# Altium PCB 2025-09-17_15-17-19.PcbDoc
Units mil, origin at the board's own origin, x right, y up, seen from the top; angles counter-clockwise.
Board outline 3850 x 3650 mil, 4 copper layers (Top Layer, MidLayer1, MidLayer2, Bottom Layer); 64 components, 29 nets, 175 pads, 336 vias.
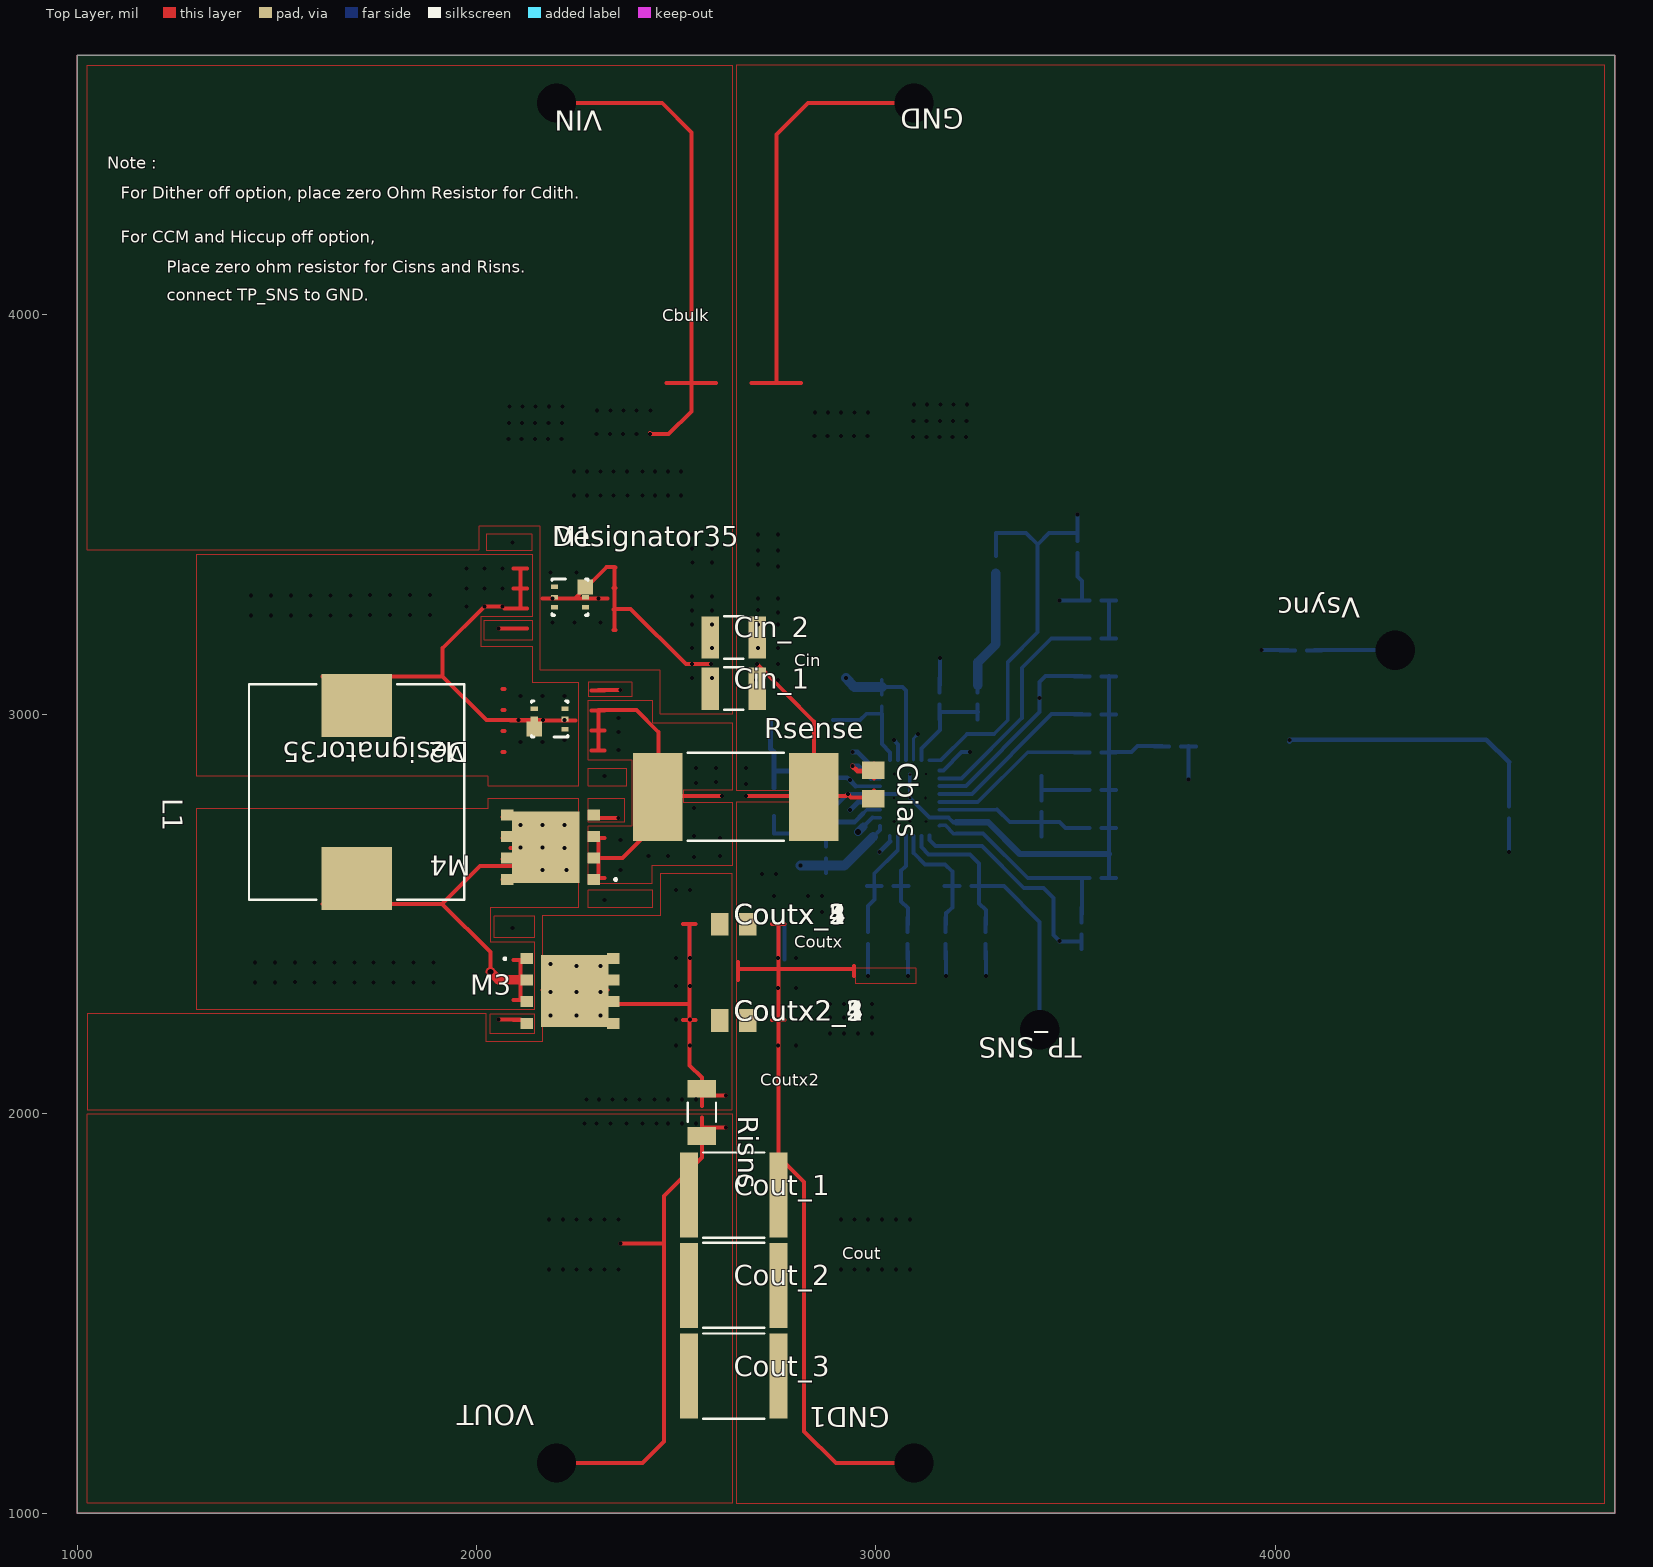
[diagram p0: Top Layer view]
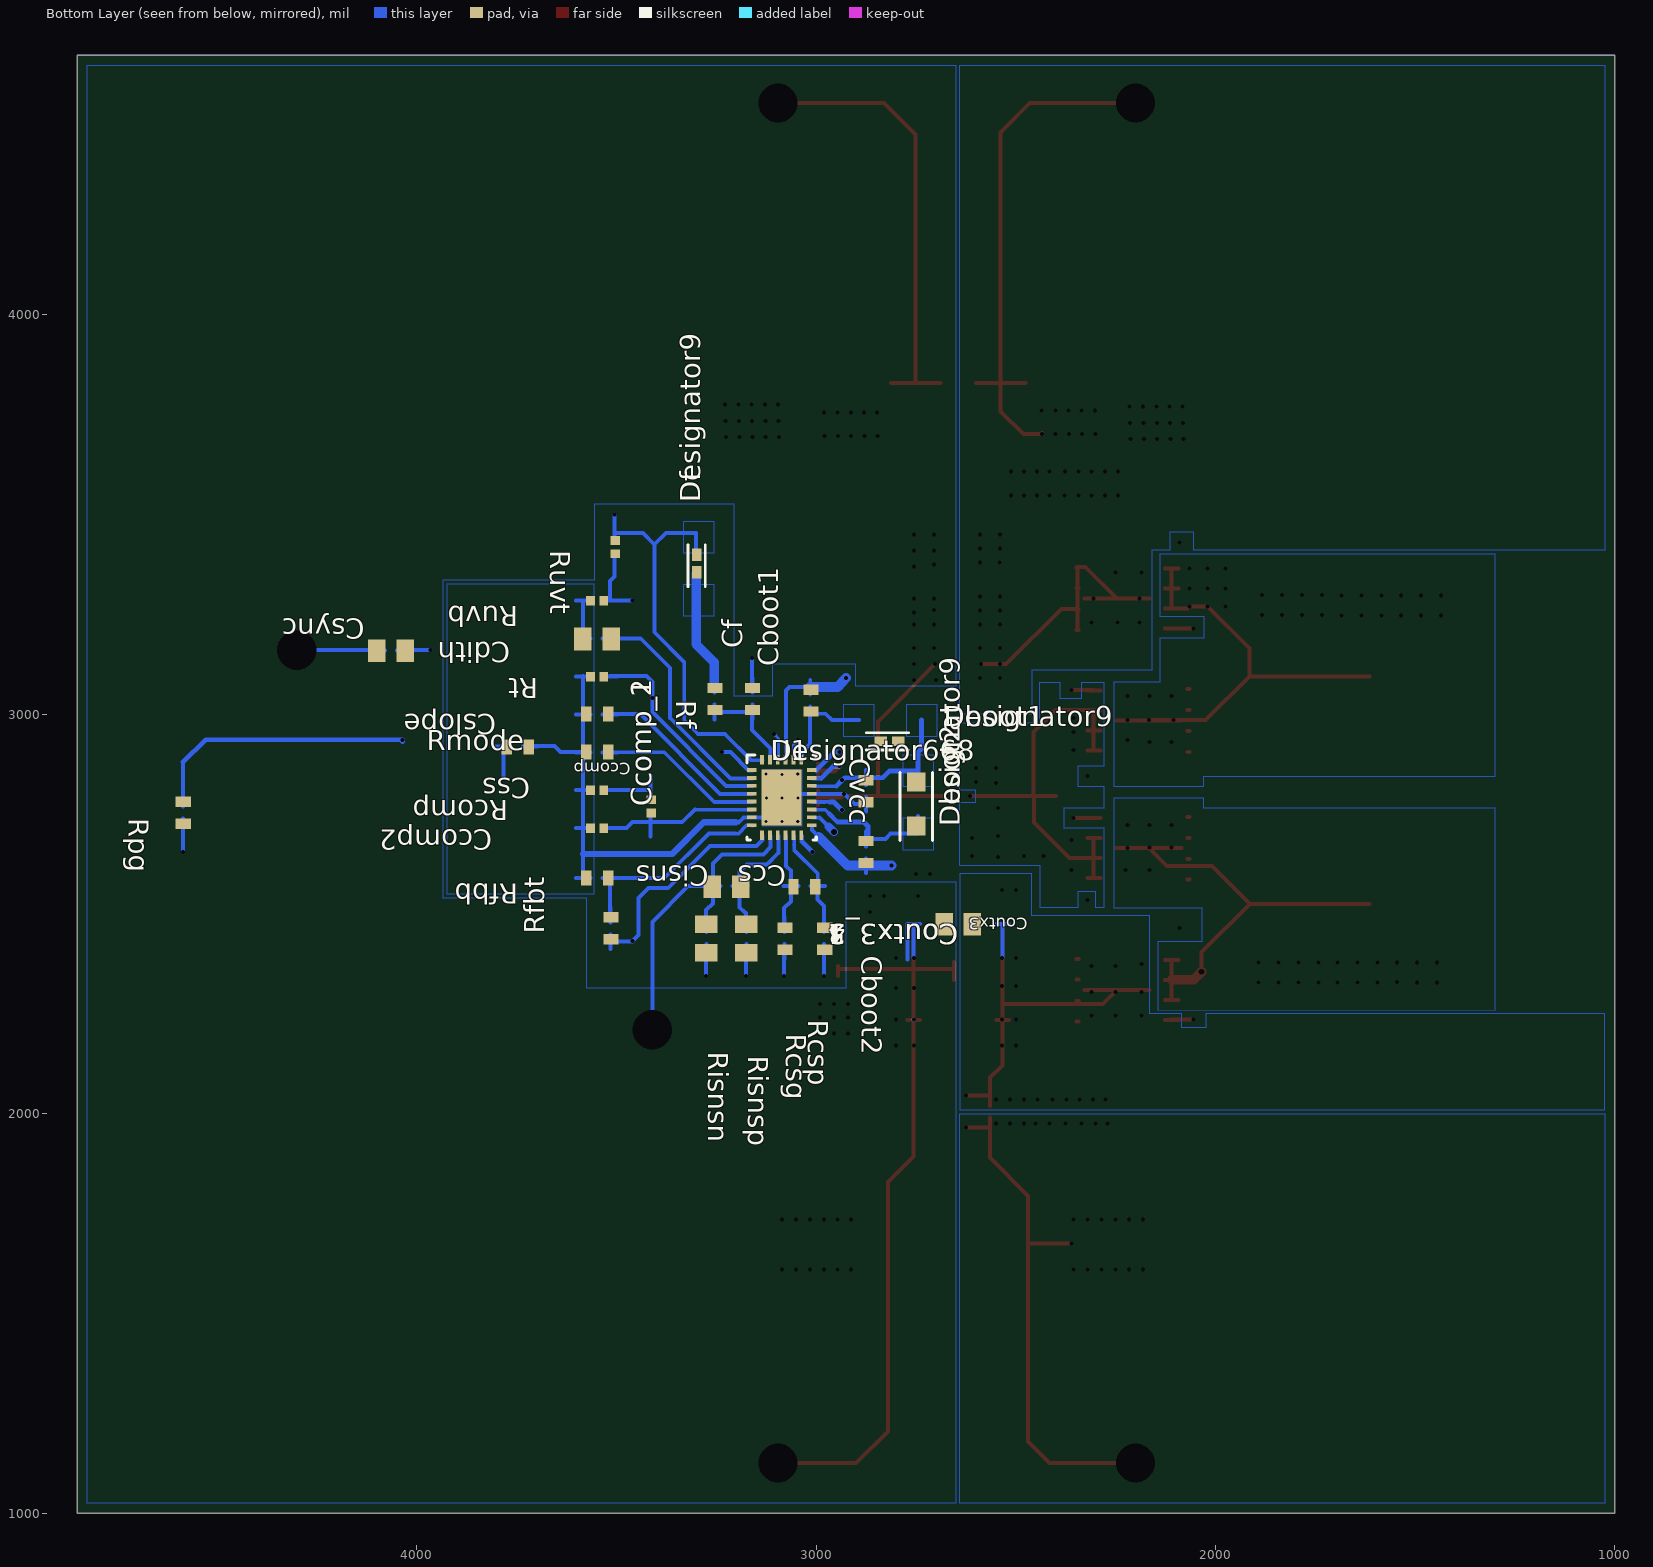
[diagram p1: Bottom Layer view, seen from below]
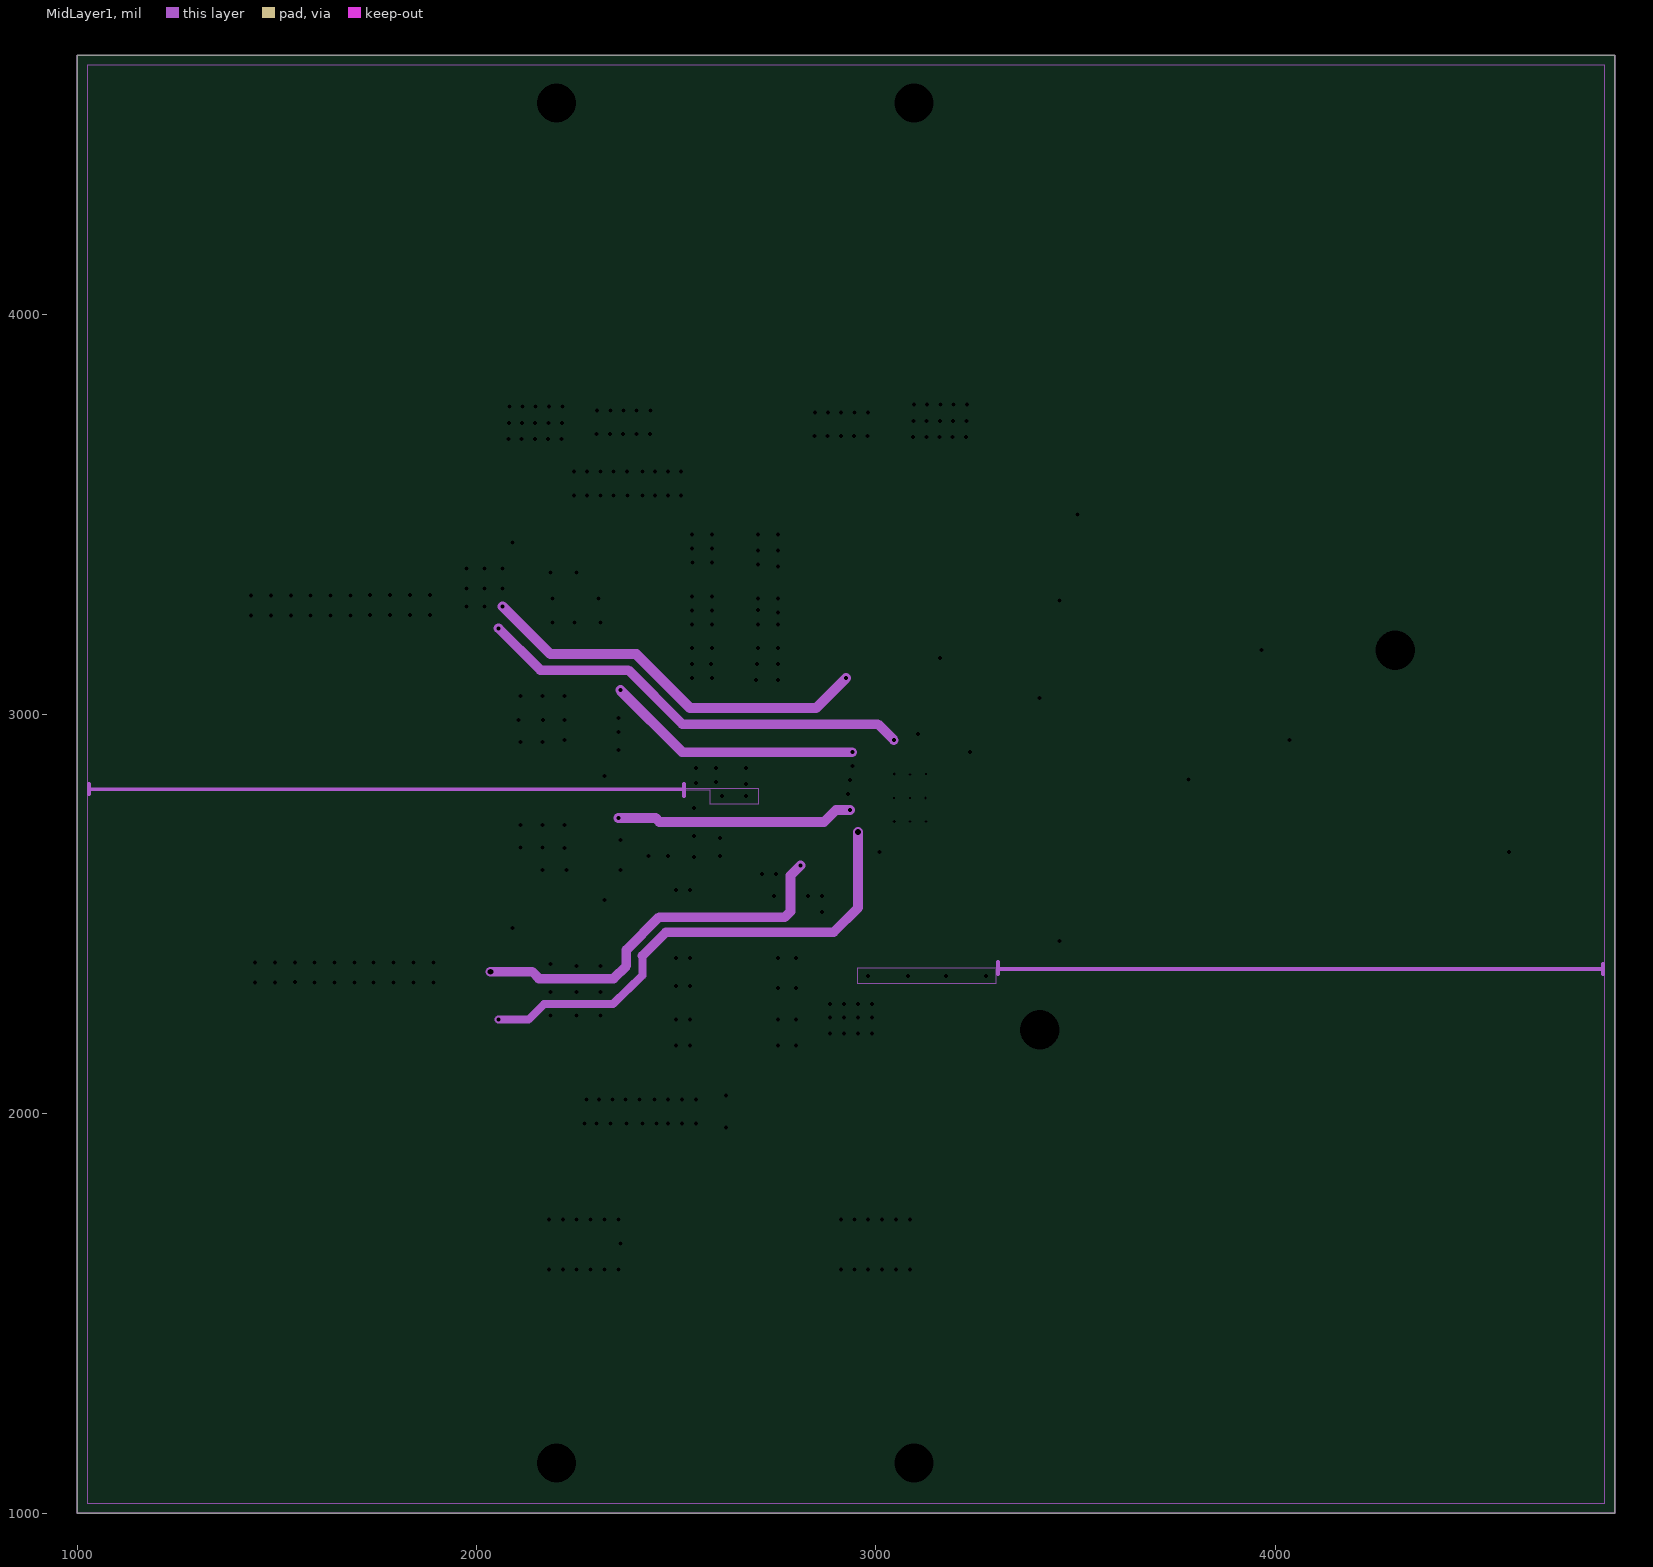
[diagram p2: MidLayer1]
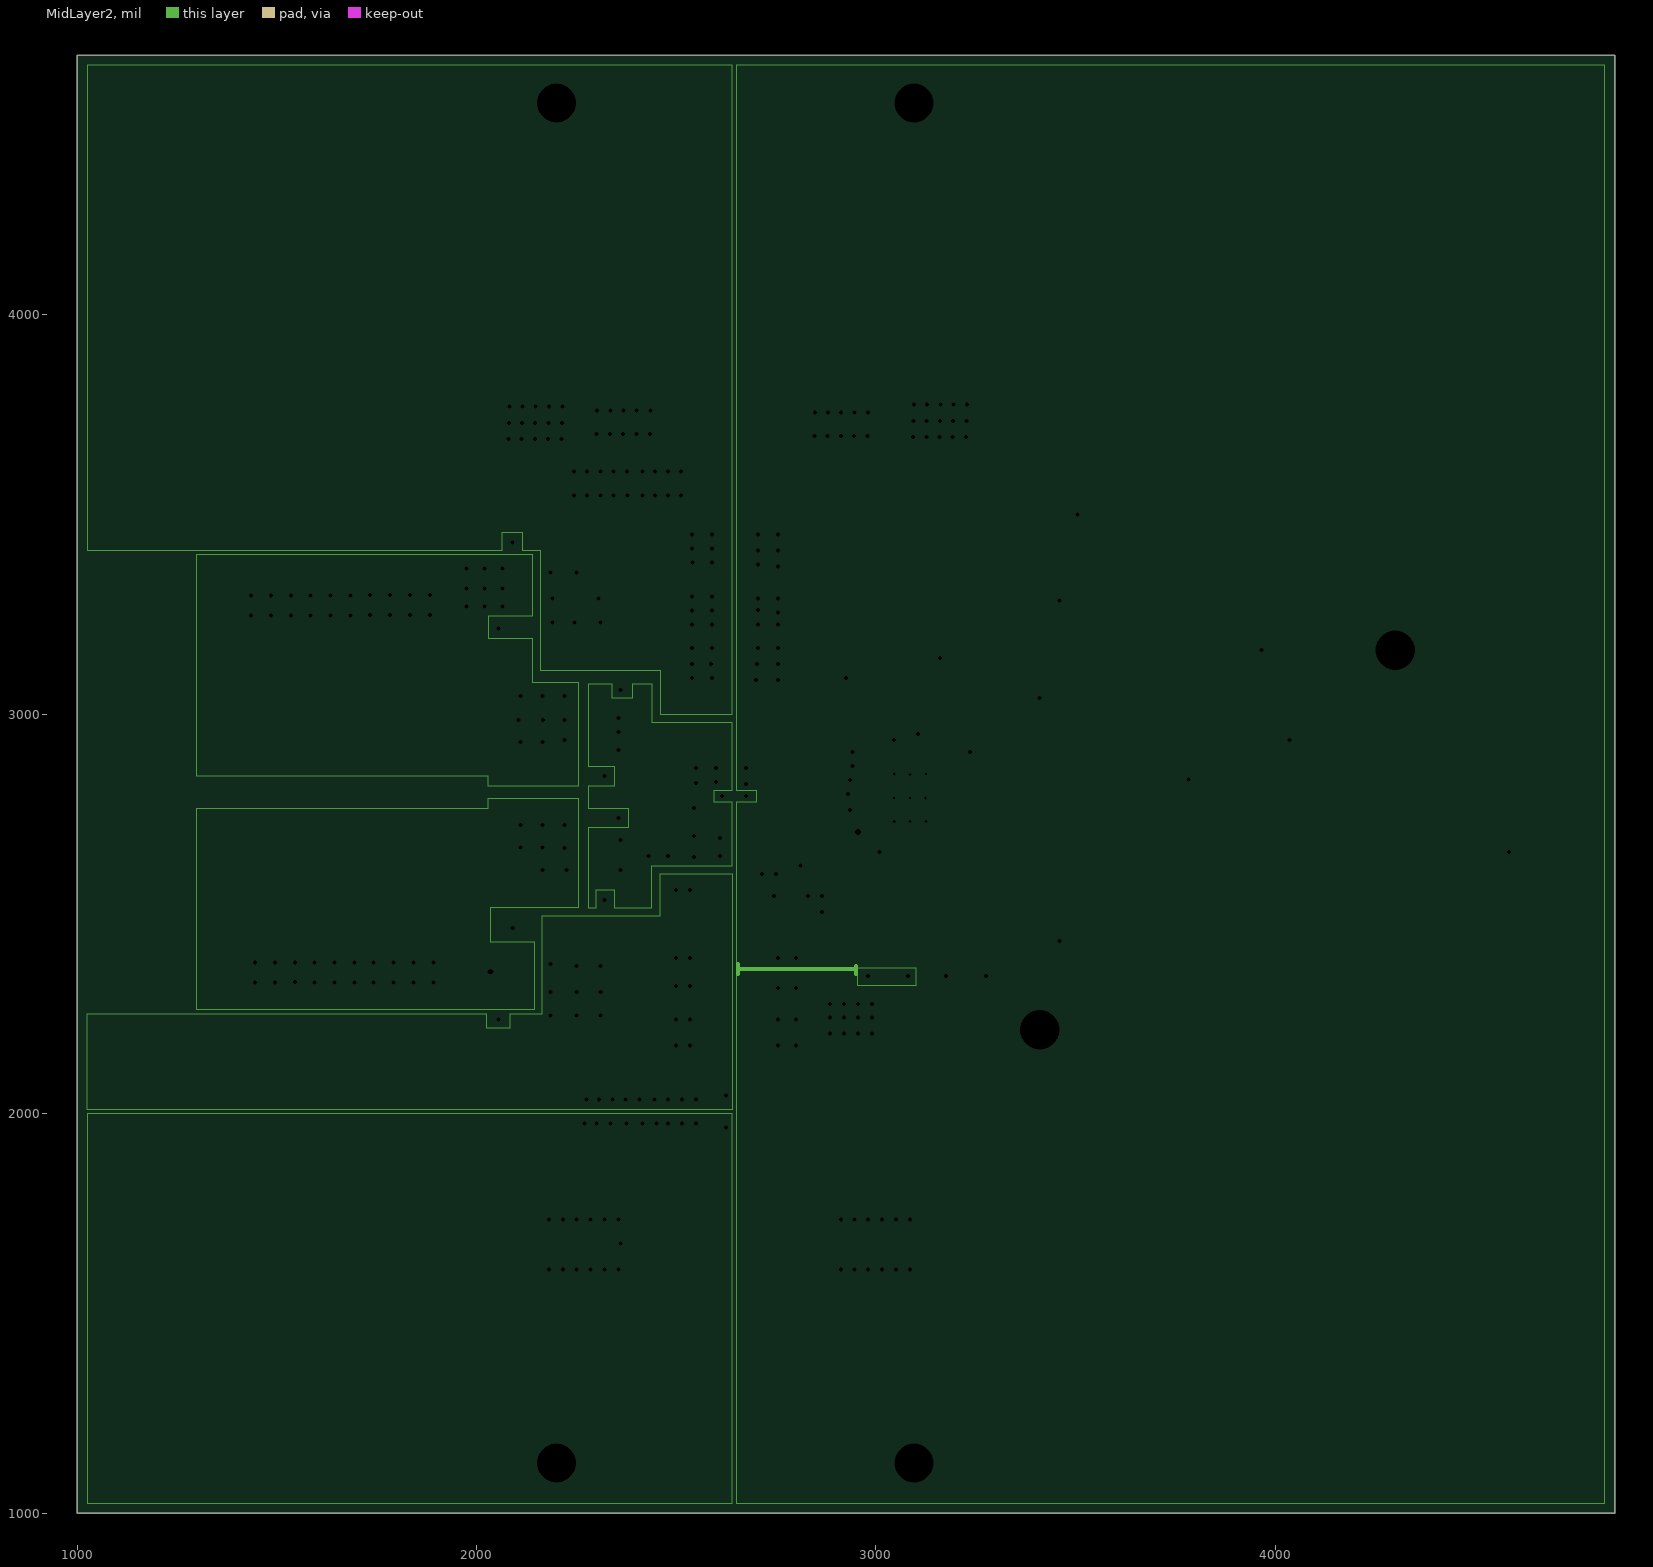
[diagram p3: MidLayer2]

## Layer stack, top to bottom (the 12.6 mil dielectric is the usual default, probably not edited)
Top Layer: signal copper 1.4
Dielectric: core 12.6, FR-4, Dk 4.8
MidLayer1: signal copper 1.4
Dielectric: prepreg 12.6, FR-4, Dk 4.8
MidLayer2: signal copper 1.4
Dielectric: core 12.6, FR-4, Dk 4.8
Bottom Layer: signal copper 1.4

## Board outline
1000,1000 4850,1000 4850,4650 1000,4650

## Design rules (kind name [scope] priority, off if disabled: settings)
PlaneConnect [All] p0: scope1count=1 scope1_0_kind=Board scope1_0_value=Board scope2count=1 scope2_0_kind=Board scope2_0_value=Board commentlength=0 planeconnectstyle=Direct reliefexpansion=20 reliefentries=4 reliefconductorwidth=10 reliefairgap=10
PlaneConnect [All] p1: planeconnectstyle=Direct reliefexpansion=20 reliefentries=4 reliefconductorwidth=10 reliefairgap=10
PolygonConnect [All] p0: scope1count=1 scope1_0_kind=Board scope1_0_value=Board scope2count=1 scope2_0_kind=Board scope2_0_value=Board commentlength=0 connectstyle=Direct reliefconductorwidth=10 reliefentries=4 polygonreliefangle="90 Angle"
PolygonConnect [All] p1: connectstyle=Direct reliefconductorwidth=10 reliefentries=4 polygonreliefangle="90 Angle"

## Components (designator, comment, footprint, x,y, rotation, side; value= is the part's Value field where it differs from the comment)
Cbias "" 0805#1 2993,2824 r270 top
Cboot1 "" 0603 3013,3034 r270 bottom
Cboot2 "" 0603 2875,2655 r90 bottom
Ccomp2 "" 0402 3548,2714 r180 bottom
Ccomp_1 "" 0402 3413,2769 r270 bottom
Ccomp_2 "" 0402 3413,2769 r270 bottom
Ccs "" 0603 3029,2568 r180 bottom
Cdith "" 0805#2 3548,3188 r180 bottom
Cf "" 0603 3159,3038 r270 bottom
Cin_1 "" 1210 2644,3064 r0 top
Cin_2 "" 1210 2644,3192 r0 top
Cisns "" 0805#2 3224,2568 r180 bottom
Cout_1 "" 2220_280 2644,1796 r0 top
Cout_2 "" 2220_280 2644,1570 r0 top
Cout_3 "" 2220_280 2644,1343 r0 top
Coutx2_1 "" 0805#1 2644,2233 r0 top
Coutx2_2 "" 0805#1 2644,2233 r0 top
Coutx2_3 "" 0805#1 2644,2233 r0 top
Coutx2_4 "" 0805#1 2644,2233 r0 top
Coutx2_5 "" 0805#1 2644,2233 r0 top
Coutx3_1 "" 0805#2 2644,2474 r180 bottom
Coutx3_2 "" 0805#2 2644,2474 r180 bottom
Coutx3_3 "" 0805#2 2644,2474 r180 bottom
Coutx3_4 "" 0805#2 2644,2474 r180 bottom
Coutx3_5 "" 0805#2 2644,2474 r180 bottom
Coutx_1 "" 0805#1 2644,2474 r0 top
Coutx_2 "" 0805#1 2644,2474 r0 top
Coutx_3 "" 0805#1 2644,2474 r0 top
Coutx_4 "" 0805#1 2644,2474 r0 top
Coutx_5 "" 0805#1 2644,2474 r0 top
Cslope "" 0603 3548,3000 r180 bottom
Css "" 0603 3548,2905 r180 bottom
Csync "" 0805#2 4064,3159 r180 bottom
Cvcc "" 0603 2875,2807 r90 bottom
Dboot1 "" SOD-523 2816,2932 r0 bottom
Dboot2 "" SOD-123F 2749,2775 r270 bottom
Df "" SOD-523 3299,3377 r270 bottom
GND "" TP-1502 3094,4529 r180 top
GND1 "" TP-1502 3094,1125 r180 top
L1 "" SRP1270 1700,2805 r270 top
M1 "" DQK0006C 2234,3293 r0 top
M2 "" DQK0006C 2183,2988 r180 top
M3 "" TRANS_NexFET_Q5A 2234,2307 r0 top
M4 "" TRANS_NexFET_Q5A 2185,2667 r180 top
Rcomp "" 0402 3548,2809 r180 bottom
Rcsg "" 0603 3078,2438 r90 bottom
Rcsp "" 0603 2978,2438 r90 bottom
Rf "" 0603 3253,3038 r90 bottom
Rfbb "" 0603 3548,2590 r180 bottom
Rfbt "" 0603 3513,2464 r270 bottom
Risns "" 1206 2564,2003 r270 top
Risnsn "" 0805#2 3275,2438 r90 bottom
Risnsp "" 0805#2 3175,2438 r90 bottom
Rmode "" 0603 3747,2918 r0 bottom
Rpg "" 0603 4584,2753 r90 bottom
Rsense "" 4527 2649,2793 r0 top
Rt "" 0402 3548,3094 r180 bottom
Ruvb "" 0402 3548,3284 r180 bottom
Ruvt "" 0402 3503,3418 r90 bottom
TP_SNS "" TP-1502 3409,2209 r180 top
U1 "" RHF0028A 3086,2791 r0 bottom
VIN "" TP-1502 2198,4529 r180 top
VOUT "" TP-1502 2198,1125 r180 top
Vsync "" TP-1502 4298,3159 r180 top

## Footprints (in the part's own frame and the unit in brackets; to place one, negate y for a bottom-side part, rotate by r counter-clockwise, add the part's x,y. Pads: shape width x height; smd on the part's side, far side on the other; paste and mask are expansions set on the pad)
0402 [mil]
  rect 22x24 smd: 1(16.5,0) 2(-16.5,0)
0603 [mil]
  rect 26x38 smd: 1(27.5,0) 2(-27.5,0)
0805#1 [mil]
  rect 44x57 smd: 1(-35.5,0) 2(35.5,0)
0805#2 [mil]
  rect 44x57 smd: 1(35.5,0) 2(-35.5,0)
1206 [mil]
  rect 44x71 smd: 1(-59,0) 2(59,0)
  silkscreen extent -24,-36 24,36
1210 [mil]
  rect 44x106 smd: 1(-59,0) 2(59,0)
  silkscreen extent -24,-53 24,53
2220_280 [mil]
  rect 45x213 smd: 1(-111.5,0) 2(111.5,0)
  silkscreen extent -76,-106 76,106
4527 [mil]
  rect 124x220 smd: 1(-195.5,0) 2(195.5,0)
  silkscreen extent -120,-110 120,110
DQK0006C [mm]
  rect 0.45x0.3 smd: 1(-0.975,0.65) 2(-0.975,0) 3(-0.975,-0.65) 4(0.975,-0.65) 5(0.975,0) 6(0.975,0.65)
  rect 0.75x0.3 smd: 6(0.975,0.65)
  rect 1x0.95 smd: 6(0.975,0.65)
  silkscreen extent -1.15,-1.15 1.15,1.15
RHF0028A [mm]
  rect 0.6x0.24 smd: 1(1.9,-1.75) 2(1.9,-1.25) 3(1.9,-0.75) 4(1.9,-0.25) 5(1.9,0.25) 6(1.9,0.75) 7(1.9,1.25) 8(1.9,1.75) 15(-1.9,1.75) 16(-1.9,1.25) 17(-1.9,0.75) 18(-1.9,0.25) 19(-1.9,-0.25) 20(-1.9,-0.75) 21(-1.9,-1.25) 22(-1.9,-1.75)
  rect 0.24x0.6 smd: 9(1.25,2.4) 10(0.75,2.4) 11(0.25,2.4) 12(-0.25,2.4) 13(-0.75,2.4) 14(-1.25,2.4) 23(-1.25,-2.4) 24(-0.75,-2.4) 25(-0.25,-2.4) 26(0.25,-2.4) 27(0.75,-2.4) 28(1.25,-2.4)
  rect 2.55x3.55 smd: 29(0,0)
  silkscreen extent -2.2,-2.7 2.2,2.7
SOD-123F [mm]
  rect 1.2x1.2 smd: 1(1.4,0) 2(-1.4,0)
  silkscreen extent -2.01,-1.03 2.31,1.03
SOD-523 [mm]
  rect 0.8x0.6 smd: 1(0.55,0) 2(-0.55,0)
  silkscreen extent -1.2,-0.55 1.48,0.55
SRP1270 [mil]
  rect 157.5x177 smd: 1(-216.75,0) 2(216.75,0)
  silkscreen extent -270,-270 270,270
TP-1502 [mil]
  round 65 hole 32: 1(0,0)
TRANS_NexFET_Q5A [mm]
  rect 0.8x0.7 smd: 1(-2.752,2.055) 2(-2.752,0.685) 3(-2.752,-0.685) 4(-2.752,-2.055) 5(2.752,-2.055) 6(2.752,-0.685) 7(2.752,0.685) 8(2.752,2.055)
  rect 4.3x4.56 smd: 9(0.3,0)
  silkscreen extent -4.22,1.98 -4.07,2.13

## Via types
v1: diameter 0, hole 10, Top Layer to Bottom Layer, 319 vias
v2: diameter 0, hole 8, Top Layer to Bottom Layer, 9 vias
v3: diameter 0, hole 98, Top Layer to Bottom Layer, 6 vias
v4: diameter 0, hole 14, Top Layer to Bottom Layer, 2 vias

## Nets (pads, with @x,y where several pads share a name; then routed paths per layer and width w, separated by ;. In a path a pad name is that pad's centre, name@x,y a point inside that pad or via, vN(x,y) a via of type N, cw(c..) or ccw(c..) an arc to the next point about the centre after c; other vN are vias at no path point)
0: Cbias.2 Ccomp2.2 Cdith.2 Cf.2 Cin_1.2 Cin_2.2 Cout_1.2 Cout_2.2 Cout_3.2 Coutx2_1.2 Coutx2_2.2 Coutx2_3.2 Coutx2_4.2 Coutx2_5.2 Coutx3_1.2 Coutx3_2.2 Coutx3_3.2 Coutx3_4.2 Coutx3_5.2 Coutx_1.2 Coutx_2.2 Coutx_3.2 Coutx_4.2 Coutx_5.2 Cslope.2 Css.2 Cvcc.2 GND1.1 GND.1 Rcomp.2 Rcsg.2 Rfbb.2 Rmode.2 Rsense.2 Rt.2 Ruvb.2 U1.7 U1.19 U1.29 | length 12480.1
  Top Layer w10: 2655,2335 2655,2362 ; 2655,2380 2655,2362 ; v1(2675,2795) Rsense.2@2845,2795 ; 2689,3829 2812,3829 ; v1(2702,3125) 2845,2981 Rsense.2@2845,2795 ; 2740,2234.5 2771,2234.5 ; 2740,2474.5 2771,2474.5 ; 2751,3830 2751,4451 2830,4530 v3(3095,4530) ; 2756,2475 2756,2362 ; Rsense.2@2790,2795 Rsense.2@2900,2795 ; 2945,2345 2945,2362 ; 2945,2370 2945,2362 ; Cbias.2@2994.5,2772 Cbias.2@2994.5,2809 ; Cbias.2@2995,2791 2938,2791 v1(2930,2800) 2925,2795 Rsense.2@2845,2795 ; v3(3095,1125) 2900,1125 2820,1204 2820,1675 2820,1829 2756,1893 2756,2235 2756,2362 ; 2655,2362 2756,2362 ; 2756,2362 2945,2362
  MidLayer1 w10: 1030,2800 1030,2812 ; 1030,2825 1030,2812 ; 2519,2812 1030,2812 ; 2520,2795 2520,2825 ; 3305,2350 3305,2362 ; 3305,2380 3305,2362 ; 4820,2350 4820,2362 ; 4820,2375 4820,2362 ; 3305,2362 4820,2362
  MidLayer2 w10: 2655,2350 2655,2362 ; 2655,2375 2655,2362 ; 2950,2350 2950,2362 ; 2950,2370 2950,2362 ; 2655,2362 2950,2362
  Mid-Layer 3 w10: 1030,2801 1030,2830 ; 1030,2812 2510,2812 ; 2510,2795 2510,2812 ; 2510,2830 2510,2812 ; 2670,2795 v1(2675,2795) 2655,2775 2655,2490 2685,2460 3010,2460 3040,2430 3040,2385 v1(3080,2345)
  Mid-Layer 4 w10: 2655,2350 2655,2362 ; 2655,2375 2655,2362 ; 2919,2362 2655,2362 ; 2920,2350 2920,2375
  Bottom Layer w9: 2962,2800 3010,2800 3045,2800 U1.29@3061,2800 ; v2(3085,2790) v2(3085,2849)
  Bottom Layer w10: 2740,2474.5 2771,2474.5 ; v1(2755,2235) 2756,2236 ; 2756,2391 2756,2475 ; 2771,2386 2771,2475 ; 2874.5,2756 2874.5,2793 ; Cvcc.2@2875,2775 2904,2775 2929,2800 ; v1(2930,2800) 2929,2800 ; 2962,2800 2929,2800 ; 3079.5,2387 3079.5,2424 ; v1(3080,2345) Rcsg.2@3080,2406 ; v2(3085,2790) 3134,2741 3159,2741 3181,2741 3194,2729 3201,2729 ; Cf.2@3159.5,3054 3159.5,3091 ; Cf.2@3160,3073 v1(3160,3140) ; Rfbb.2@3564,2589.5 3601,2589.5 ; Ccomp2.2@3564,2714.5 3601,2714.5 ; Rcomp.2@3564,2809.5 3601,2809.5 ; Css.2@3564,2904.5 3601,2904.5 ; Cslope.2@3564,2999.5 3601,2999.5 ; Rt.2@3564,3094.5 3601,3094.5 ; Cdith.2@3564,3189.5 Cdith.2@3601,3189.5 ; Ruvb.2@3564,3284.5 3601,3284.5 ; Rfbb.2@3583,2590 3583,2650 3583,2715 3583,2810 Css.2@3583,2905 ; 3583,3095 3583,3000 Css.2@3583,2905 ; Cdith.2@3583,3190 3583,3285 ; 3697,2919.5 3734,2919.5 ; Rmode.2@3716,2920 3655,2920 3640,2905 Css.2@3583,2905
  Bottom Layer w16: 3201,2729 3281,2729 3360,2650 3583,2650
  other v1: 2912,1610 2946,1610 2980,1610 3015,1610 3050,1610 3085,1610 2912,1735 2946,1735 2980,1735 3015,1735 3050,1735 3085,1735 2755,2170 2800,2170 2885,2200 2920,2200 2955,2200 2990,2200 2800,2235 2885,2240 2920,2240 2955,2240 2990,2240 2885,2275 2920,2275 2955,2275 2990,2275 2755,2315 2800,2315 2755,2390 2800,2390 2865,2505 2745,2545 2830,2545 2865,2545 2715,2600 2750,2600 2675,2825 2675,2865 2700,3085 2755,3085 2755,3125 2705,3165 2755,3165 2705,3225 2755,3225 2755,3255 2705,3261 2705,3290 2755,3290 2755,3370 2705,3375 2705,3410 2755,3410 2705,3450 2755,3450 3093,3694 3126,3694 3159,3694 3192,3694 3226,3694 2846,3696 2879,3696 2912,3696 2945,3696 2979,3696 3094,3734 3127,3734 3160,3734 3193,3734 3227,3734 2847,3755 2880,3755 2913,3755 2946,3755 2980,3755 3095,3775 3128,3775 3161,3775 3194,3775 3228,3775
  other v2: 3046,2731 3085,2731 3125,2731 3045,2790 3124,2790 3046,2850 3125,2850
1: Cin_1.1 Cin_2.1 Df.2 M1.1 M1.2 M1.3 M1.5 M1.6 Ruvt.1 U1.28 VIN.1 | length 4321.1
  Top Layer w10: 2165,3289.5 2328,3289.5 ; v3(2200,4530) 2465,4530 2538,4456 2538,3830 2538,3758 2481,3701 v1(2434,3701) 2434,3704 ; 2247,3290 2326,3368 2346,3368 2346,3316 2346,3263 ; 2343,3210.5 2348,3210.5 ; 2343,3262.5 2348,3262.5 ; 2343,3315.5 2348,3315.5 ; 2343,3367.5 2348,3367.5 ; 2346,3211 2346,3263 ; 2476,3829 2599,3829 ; v1(2587,3125) v1(2540,3125) 2525,3125 2386,3263 2346,3263
  Mid-Layer 3 w10: v1(2434,3701) 2544,3701 2745,3500 v1(3505,3500)
  Bottom Layer w9: U1.28@3134,2885 3163,2885 3228,2950 ; 3295,2950 3330,2985 3330,3131
  Bottom Layer w10: 3228,2950 3295,2950 ; Df.2@3300,3396 3300,3453 3376,3453 3405,3425 ; 3330,3131 3405,3206 3405,3425 ; Ruvt.1@3504.5,3434 3504.5,3471 ; v1(3505,3500) 3505,3453 3433,3453 3405,3425
  other v1: 2540,3090 2590,3090 2540,3165 2590,3165 2540,3225 2590,3225 2190,3230 2245,3230 2310,3230 2540,3260 2590,3260 2190,3290 2305,3290 2540,3295 2590,3295 2185,3355 2250,3355 2541,3380 2590,3380 2540,3415 2590,3415 2540,3450 2590,3450 2244,3547 2277,3547 2310,3547 2343,3547 2378,3547 2415,3547 2447,3547 2479,3547 2512,3547 2244,3608 2277,3608 2310,3608 2343,3608 2377,3608 2415,3608 2447,3608 2479,3608 2512,3608 2080,3689 2113,3689 2146,3689 2179,3689 2213,3689 2301,3701 2334,3701 2367,3701 2400,3701 2081,3729 2114,3729 2147,3729 2180,3729 2214,3729 2302,3760 2335,3760 2368,3760 2401,3760 2435,3760 2082,3770 2115,3770 2148,3770 2181,3770 2215,3770
2: Rmode.1 U1.1 | length 792.2
  Mid-Layer 3 w10: v1(3235,2905) 3712,2905 3736,2880 3737,2880 3781,2836 v1(3782,2836)
  Bottom Layer w9: U1.1@3159,2859 U1.1@3169,2859
  Bottom Layer w10: U1.1@3169,2859 3214,2905 v1(3235,2905) ; Rmode.1@3764,2919.5 3801,2919.5 ; v1(3782,2836) 3782,2870 Rmode.1@3782,2920
4: Ccomp_1.2 Ccomp_2.2 Rcomp.1 | length 199
  Bottom Layer w10: Ccomp_1.2@3414,2784 3414,2845 ; 3415,2810 3516,2810 ; 3497,2809.5 Rcomp.1@3534,2809.5
5: Ccomp2.1 Ccomp_1.1 Ccomp_2.1 U1.6 | length 473.8
  Bottom Layer w9: U1.6@3159,2761 3303,2761
  Bottom Layer w10: 3303,2761 3335,2730 3415,2730 3460,2730 3475,2715 3516,2715 ; 3414,2694 Ccomp_1.1@3414,2755 ; 3497,2714.5 Ccomp2.1@3534,2714.5
6: Ruvb.1 Ruvt.2 U1.26 | length 798.6
  Mid-Layer 3 w10: v1(3105,2950) 3440,3285 v1(3460,3285)
  Bottom Layer w8: U1.26@3094,2885 3094,2939 v1(3105,2950)
  Bottom Layer w10: v1(3460,3285) 3516,3285 3516,3333 3505,3345 3505,3386 ; 3497,3284.5 Ruvb.1@3534,3284.5 ; 3504.5,3367 Ruvt.2@3504.5,3404
9: Cf.1 Rf.2 U1.27 | length 309.1
  Bottom Layer w10: U1.27@3114,2885 3114,2914 3160,2960 3160,3006 Rf.2@3255,3006 ; 3159.5,2987 3159.5,3024 ; 3254.5,2987 3254.5,3024
10: Ccs.1 Rcsp.1 U1.13 | length 328.1
  Bottom Layer w9: Ccs.1@2996,2570 2996,2601 3055,2660 U1.13@3055,2696
  Bottom Layer w10: 2977,2569.5 Ccs.1@3014,2569.5 ; Rcsp.1@2979.5,2454 2979.5,2491 ; Rcsp.1@2980,2473 2980,2520 2996,2536 Ccs.1@2996,2570
12: Ccs.2 Rcsg.1 U1.12 | length 309.3
  Bottom Layer w10: Ccs.2@3044,2569.5 3081,2569.5 ; U1.12@3075,2696 3075,2620 3063,2608 3063,2570 3063,2531 3080,2515 Rcsg.1@3080,2473 ; Rcsg.1@3079.5,2454 3079.5,2491
16: Cboot1.1 Dboot1.1 Rpg.2 U1.14 U1.23 | length 2020.4
  Mid-Layer 3 w10: v1(3009,2655) v1(4585,2655)
  Bottom Layer w9: 3035,2681 U1.14@3035,2696
  Bottom Layer w10: 2893,2985 2960,2985 2976,3001 3015,3001 3015,2925 3035,2904 U1.23@3035,2885 ; 3014.5,2982 Cboot1.1@3014.5,3019 ; 4584.5,2702 4584.5,2739 ; v1(4585,2655) Rpg.2@4585,2721
  Bottom Layer w12: v1(3009,2655) 3035,2681
17: Cout_1.1 Cout_2.1 Cout_3.1 Coutx2_1.1 Coutx2_2.1 Coutx2_3.1 Coutx2_4.1 Coutx2_5.1 Coutx3_1.1 Coutx3_2.1 Coutx3_3.1 Coutx3_4.1 Coutx3_5.1 Coutx_1.1 Coutx_2.1 Coutx_3.1 Coutx_4.1 Coutx_5.1 M3.5 M3.6 M3.7 M3.8 M3.9 Rfbt.1 Risns.1 Risns.2 Risnsn.2 Risnsp.2 U1.9 VOUT.1 | length 7128.4
  Top Layer w10: M3.9@2165,2309.5 M3.9@2328,2309.5 ; v3(2200,1125) 2415,1125 2469,1179 2469,1675 ; M3.9@2247,2310 2282,2275 2533,2275 ; M3.5@2343,2230.5 M3.5@2348,2230.5 ; M3.6@2343,2282.5 M3.6@2348,2282.5 ; M3.7@2343,2335.5 M3.7@2348,2335.5 ; M3.8@2343,2387.5 M3.8@2348,2387.5 ; v1(2360,1675) 2469,1675 ; 2517,2234.5 2548,2234.5 ; 2517,2474.5 2548,2474.5 ; 2533,2475 2533,2275 ; Risns.2@2564,1929 2564,1990 ; 2564,2019 Risns.1@2564,2080 ; v1(2625,1965) 2565,1965 2565,1890 2469,1794 2469,1675 ; v1(2625,2045) 2565,2045 2565,2090 2533,2121 2533,2235 2533,2275
  Mid-Layer 3 w10: v1(2360,1675) 3400,1675 3530,1805 3530,2362 v1(3460,2432) ; v1(2625,1965) 2655,1995 3190,1995 3235,2040 3235,2305 v1(3275,2345) ; v1(2625,2045) 2655,2015 3180,2015 3215,2050 3215,2305 v1(3175,2345)
  Bottom Layer w10: 2517,2474.5 2548,2474.5 ; 2533,2391 2533,2475 ; U1.9@3134,2696 3134,2685 3149,2670 3265,2670 3370,2565 3420,2565 3445,2540 3445,2447 v1(3460,2432) 3460,2431 Rfbt.1@3515,2431 ; Risnsp.2@3174.5,2387 Risnsp.2@3174.5,2424 ; v1(3175,2345) Risnsp.2@3175,2406 ; Risnsn.2@3274.5,2387 Risnsn.2@3274.5,2424 ; v1(3275,2345) Risnsn.2@3275,2406 ; 3514.5,2412 Rfbt.1@3514.5,2449
  other v1: 2182,1610 2216,1610 2250,1610 2285,1610 2320,1610 2355,1610 2182,1735 2216,1735 2250,1735 2285,1735 2320,1735 2355,1735 2270,1975 2300,1975 2335,1975 2375,1975 2415,1975 2450,1975 2480,1975 2515,1975 2550,1975 2275,2035 2307,2035 2340,2035 2373,2035 2408,2035 2445,2035 2480,2035 2515,2035 2550,2035 2500,2170 2535,2170 2500,2235 2535,2235 2185,2245 2250,2245 2310,2245 2185,2305 2250,2305 2310,2305 2500,2320 2535,2320 2250,2370 2310,2370 2185,2375 2500,2390 2535,2390 2500,2560 2535,2560
18: Csync.1 Cvcc.1 Dboot1.2 Dboot2.2 Rpg.1 Rt.1 U1.3 U1.20 | length 3600.1
  Mid-Layer 3 w10: 3409,3039 3844,3039 v1(3965,3160)
  Mid-Layer 3 w12: v1(2935,2835) 2970,2835 3030,2895 3134,2895 3174,2935 v1(4035,2935)
  Bottom Layer w9: 2949,2820 U1.20@3010,2820
  Bottom Layer w10: Cvcc.1@2874.5,2823 2874.5,2860 ; U1.3@3159,2820 3225,2820 3410,3005 v1(3410,3040) 3410,3080 3425,3095 3516,3095 ; 3497,3094.5 Rt.1@3534,3094.5 ; v1(3965,3160) Csync.1@4031,3160 ; Csync.1@4012,3159.5 Csync.1@4049,3159.5 ; Rpg.1@4584.5,2769 4584.5,2806 ; Rpg.1@4585,2788 4585,2880
  Bottom Layer w12: 2736,2985 2736,2913 2745,2905 2745,2858 ; Dboot2.2@2745,2815 2745,2858 ; 2949,2820 v1(2935,2835) 2928,2841 2875,2841 2833,2841 2816,2858 2745,2858 ; 4035,2931 v1(4035,2935) ; 4035,2936 4528,2936 4585,2880
21: M2.4 M4.1 M4.2 M4.3 Rcsp.2 Rsense.1 | length 2178.9
  Top Layer w10: M4.1@2288,2589.5 2321,2589.5 ; M4.2@2288,2639.5 2321,2639.5 ; M4.3@2288,2689.5 2321,2689.5 ; 2288,2909.5 2321,2909.5 ; 2288,2959.5 2321,2959.5 ; 2288,3009.5 2321,3009.5 ; M4.1@2305,2590 M4.2@2305,2640 ; M4.3@2305,2690 M4.2@2305,2640 ; 2305,2910 2305,2960 2305,3010 2400,3010 2455,2955 2455,2795 Rsense.1@2454,2795 ; Rsense.1@2399,2795 Rsense.1@2509,2795 ; v1(2615,2795) Rsense.1@2454,2795 ; M4.2@2305,2640 2365,2640 2454,2729 Rsense.1@2454,2795
  Mid-Layer 3 w10: v1(2615,2795) 2615,2790 2635,2770 2635,2485 2680,2440 3000,2440 3020,2420 3020,2385 v1(2980,2345) ; 2978,2340 2980,2344
  Bottom Layer w10: 2979.5,2387 2979.5,2424 ; v1(2980,2345) Rcsp.2@2980,2406
  other v1: 2360,2610 2545,2643 2430,2645 2480,2645 2610,2645 2360,2685 2610,2690 2545,2695 2545,2765 2549,2828 2600,2830 2550,2865 2600,2865 2355,2910 2355,2955 2355,2990
22: Cboot1.2 L1.1 M1.4 M2.1 M2.2 M2.3 M2.5 M2.6 U1.25 | length 2661.3
  Top Layer w10: L1.1@1615,3094 1915,3094 ; 2065,2905.5 2070,2905.5 ; 2065,2957.5 2070,2957.5 ; 2065,3010.5 2070,3010.5 ; 2065,3062.5 2070,3062.5 ; 2085,2984.5 2248,2984.5 ; 2093,3264.5 2126,3264.5 ; 2093,3314.5 2126,3314.5 ; 2093,3364.5 2126,3364.5 ; 2110,3365 2110,3315 2110,3265 2070,3265 v1(2065,3270) v1(2020,3270) 1915,3165 1915,3094 ; v1(2167,2985) v1(2105,2985) 2025,2985 1915,3094
  MidLayer1 w25: v1(2065,3270) 2185,3150 2400,3150 2535,3015 2850,3015 v1(2925,3090)
  Bottom Layer w10: Cboot1.2@3014.5,3049 3014.5,3086 ; Cboot1.2@3015,3068 3066,3068 3075,3059 U1.25@3075,2885
  Bottom Layer w25: v1(2925,3090) 2946,3068 Cboot1.2@3015,3068
  other v1: 2110,2930 2165,2930 2220,2935 2220,2985 2110,3045 2165,3045 2220,3045 1435,3247 1485,3247 1535,3247 1585,3247 1635,3247 1685,3247 1733,3248 1783,3248 1833,3248 1883,3248 1975,3270 1435,3297 1485,3297 1535,3297 1585,3297 1635,3297 1685,3297 1733,3298 1783,3298 1833,3298 1883,3298 1975,3315 2020,3315 2065,3315 1975,3365 2020,3365 2065,3365
24: Cboot2.1 Dboot2.1 U1.17 | length 400.7
  Bottom Layer w9: 2968,2752 2977,2761 U1.17@3010,2761
  Bottom Layer w10: 2745,2745 2745,2701 2813,2701 2826,2688 Cboot2.1@2870,2688 ; 2874.5,2669 2874.5,2706
  Bottom Layer w12: Cboot2.1@2870,2688 2870,2720 2880,2730 2947,2730 2968,2752
25: Cboot2.2 L1.2 M3.1 M3.2 M3.3 M4.5 M4.6 M4.7 M4.8 M4.9 U1.15 | length 2556.3
  Top Layer w10: L1.2@1615,2525 1914,2525 ; v4(2035,2355) 2035,2405 1914,2525 ; M4.8@2065,2585.5 M4.8@2070,2585.5 ; M4.7@2065,2637.5 M4.7@2070,2637.5 ; M4.6@2065,2690.5 M4.6@2070,2690.5 ; M4.5@2065,2742.5 M4.5@2070,2742.5 ; 2085,2664.5 M4.9@2248,2664.5 ; 2093,2284.5 M3.3@2126,2284.5 ; 2093,2334.5 M3.2@2126,2334.5 ; 2093,2384.5 M3.1@2126,2384.5 ; M3.3@2110,2285 2110,2335 M3.1@2110,2385 ; M4.9@2167,2665 2122,2620 2009,2620 1914,2525
  Top Layer w24: v4(2035,2355) 2055,2335 M3.2@2110,2335
  MidLayer1 w24: v4(2035,2355) 2140,2355 2156,2338 2343,2338 2375,2370 2375,2410 2457,2492 2772,2492 2786,2506 2786,2596 v1(2811,2621)
  Bottom Layer w9: 2993,2693 3010,2710 U1.15@3010,2721
  Bottom Layer w10: 2874.5,2602 Cboot2.2@2874.5,2639
  Bottom Layer w24: v1(2811,2621) 2875,2621 2921,2621 2986,2686 2993,2693
  other v1: 1445,2328 1495,2328 1595,2328 1645,2328 1695,2328 1742,2328 1792,2328 1842,2328 1892,2328 1545,2329 1445,2378 1495,2378 1545,2378 1595,2378 1645,2378 1695,2378 1742,2378 1792,2378 1842,2378 1892,2378 2165,2610 2225,2610 2220,2665 2110,2666 2165,2666 2110,2722 2165,2722 2220,2722
29: Df.1 Rf.1 | length 335.6
  Bottom Layer w10: Rf.1@3254.5,3054 3254.5,3091
  Bottom Layer w24: Rf.1@3255,3073 3255,3130 3300,3175 Df.1@3300,3353
30: Rfbb.1 Rfbt.2 U1.8 | length 578.3
  Bottom Layer w9: U1.8@3159,2721 3160,2722 3174,2722 3194,2701 3201,2701
  Bottom Layer w10: 3201,2701 3268,2701 3380,2590 3516,2590 3516,2500 Rfbt.2@3515,2498 ; 3497,2589.5 3534,2589.5 ; Rfbt.2@3514.5,2479 3514.5,2516
34: Cbias.1 U1.21 | length 178.1
  Top Layer w10: Cbias.1@2994.5,2839 Cbias.1@2994.5,2876
  Top Layer w12: v1(2941,2870) 2953,2858 Cbias.1@2995,2858
  Bottom Layer w9: 2987,2839 U1.21@3010,2839
  Bottom Layer w12: v1(2941,2870) 2957,2870 2987,2839
37: Cdith.1 U1.2 | length 612.6
  Bottom Layer w10: U1.2@3159,2839 3214,2839 3365,2990 3365,3115 3440,3190 Cdith.1@3516,3190 ; Cdith.1@3497,3189.5 Cdith.1@3534,3189.5
41: U1.24 | length 1508.6
  Top Layer w10: v1(2055,3215) 2110,3215 ; 2093,3214.5 2126,3214.5
  MidLayer1 w24: v1(2055,3215) 2160,3110 2380,3110 2515,2975 3005,2975 v1(3045,2935)
  Mid-Layer 3 w24: v1(2055,3215) 2080,3215 2110,3245 2110,3410 v1(2090,3430)
  Bottom Layer w10: v1(3045,2935) 3055,2924 U1.24@3055,2885
42: M3.4 U1.16 | length 1636.8
  Top Layer w10: v1(2055,2235) M3.4@2110,2235 ; 2093,2234.5 M3.4@2126,2234.5
  MidLayer1 w20: v1(2055,2235) 2130,2235 2169,2274 2342,2274 2415,2346 2415,2395
  MidLayer1 w24: 2415,2395 2474,2454 2894,2454 2955,2515 v4(2955,2705)
  Mid-Layer 3 w20: v1(2055,2235) 2090,2270 v1(2090,2465)
  Bottom Layer w9: 2991,2741 U1.16@3010,2741
  Bottom Layer w10: 2969,2719 2991,2741
  Bottom Layer w20: v4(2955,2705) 2969,2719
43: U1.22 | length 1042.1
  Top Layer w10: 2288,3059.5 2321,3059.5 ; 2305,3060 v1(2360,3060)
  MidLayer1 w24: 2515,2905 v1(2941,2905)
  MidLayer1 w25: v1(2360,3060) 2515,2905
  Mid-Layer 3 w25: v1(2320,2845) 2320,3020 v1(2360,3060)
  Bottom Layer w12: v1(2941,2905) 2954,2905 2999,2859
44: M4.4 U1.18 | length 984.1
  Top Layer w10: M4.4@2288,2739.5 2321,2739.5 ; M4.4@2305,2740 v1(2355,2740)
  MidLayer1 w24: v1(2355,2740) 2449,2740 2458,2730 2870,2730 2900,2760 v1(2935,2760)
  Mid-Layer 3 w25: v1(2320,2535) 2320,2705 v1(2355,2740)
  Bottom Layer w9: 2966,2780 2967,2781 2977,2781 2977,2780 U1.18@3010,2780
  Bottom Layer w12: v1(2935,2760) 2955,2780 2966,2780
48: Css.1 U1.5 | length 445.8
  Bottom Layer w9: U1.5@3159,2780 3255,2780 3380,2905 Css.1@3516,2905
  Bottom Layer w10: 3497,2904.5 3534,2904.5
51: Cisns.2 Risnsn.1 TP_SNS.1 U1.10 | length 883.6
  Bottom Layer w9: 3114,2667 U1.10@3114,2696
  Bottom Layer w10: 3114,2667 3132,2649 3235,2649 3258,2626 Cisns.2@3258,2570 ; Cisns.2@3239,2569.5 Cisns.2@3276,2569.5 ; Risnsn.1@3274.5,2454 Risnsn.1@3274.5,2491 ; Risnsn.1@3275,2473 3275,2510 3258,2526 Cisns.2@3258,2570 ; v3(3410,2210) 3410,2480 3320,2570 Cisns.2@3258,2570
52: Cisns.1 Risnsp.1 U1.11 | length 374.3
  Bottom Layer w9: 3094,2653 U1.11@3094,2696
  Bottom Layer w10: 3094,2653 3123,2624 3173,2624 3191,2606 3191,2570 3191,2516 3177,2502 3175,2502 Risnsp.1@3175,2473 ; Cisns.1@3172,2569.5 Cisns.1@3209,2569.5 ; Risnsp.1@3174.5,2454 Risnsp.1@3174.5,2491
53: Cslope.1 U1.4 | length 476.8
  Bottom Layer w9: U1.4@3159,2800 3240,2800
  Bottom Layer w10: 3240,2800 3440,3000 Cslope.1@3516,3000 ; 3497,2999.5 3534,2999.5
62: Csync.2 Vsync.1 | length 269
  Bottom Layer w10: Csync.2@4079,3159.5 Csync.2@4116,3159.5 ; Csync.2@4098,3160 v3(4300,3160) ; Vsync.1@4300,3150 4330,3150

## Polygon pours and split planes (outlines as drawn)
10 on Bottom Layer " " (solid, pour order 0): 3055,2673 3059,2673
29 on Bottom Layer " " (solid, pour order 1): 3255,3246 3255,3324 3333,3324 3333,3246
1 on Bottom Layer " " (solid, pour order 2): 3255,3404 3255,3482 3333,3482 3333,3404
24 on Bottom Layer " " (solid, pour order 3): 2705,2661 2705,2739 2783,2739 2783,2661
18 on Bottom Layer " " (solid, pour order 4): 2705,2819 2705,2897 2783,2897 2783,2819
16 on Bottom Layer " " (solid, pour order 5): 2854,2945 2854,3023 2932,3023 2932,2945
18 on Bottom Layer " " (solid, pour order 6): 2696,2945 2696,3023 2774,3023 2774,2945
17 on Bottom Layer " " (solid, pour order 27): 1025,1025 2640,1025 2640,2000 1025,2000
22 on Bottom Layer " " (solid, pour order 28): 2140,3245 2030,3245 2030,3190 2140,3190 2140,3080 2255,3080 2255,2820 2030,2820 2030,2845 1300,2845 1300,3400 2140,3400
17 on Bottom Layer " " (solid, pour order 29): 2025,2250 2025,2215 2085,2215 2085,2250 2165,2250 2165,2495 2460,2495 2460,2600 2640,2600 2640,2010 1025,2010 1025,2250
21 on Bottom Layer " " (solid, pour order 30): 2280,2765 2380,2765 2380,2715 2280,2715 2280,2515 2300,2515 2300,2555 2345,2555 2345,2515 2439,2515 2439,2620 2640,2620 2640,2780 2600,2780 2600,2810 2640,2810 2640,2979 2499,2979 2440,2979 2440,3080 2390,3080 2390,3040 2335,3040 2335,3080 2280,3080 2280,2870 2345,2870 2345,2820 2280,2820
25 on Bottom Layer " " (solid, pour order 31): 2145,2515 2035,2515 2035,2430 2145,2430 2145,2361 2145,2260 1300,2259 1300,2765 2030,2765 2030,2790 2255,2790 2255,2515
1 on Bottom Layer " " (solid, pour order 32): 2055,3410 2055,3455 2115,3455 2115,3410 2160,3410 2160,3110 2460,3110 2460,3000 2640,3000 2640,4625 1025,4625 1025,3410
0 on Bottom Layer " " (solid, pour order 43): 3925,3324 3925,2550 3555,2550 3555,3325 3924,3325
0 on Bottom Layer " " (solid, pour order 44): 3110,3125 3110,3045 3205,3045 3205,3525 3555,3525 3555,3335 3935,3335 3935,2540 3575,2540 3575,2315 2925,2315 2925,2580 2650,2580 2650,1025 4825,1025 4824,4625 4793,4625 2650,4625 2650,3070 2900,3070 2900,3125
0 on Bottom Layer " " (solid, pour order 45): 3135,2720 3035,2720 3035,2860 3135,2860
17 on Top Layer " " (solid, pour order 13): 2640,2000 2640,1025 1025,1025 1025,2000
41 on Top Layer " " (solid, pour order 14): 2140,3185 2020,3185 2020,3235 2140,3235
17 on Top Layer " " (solid, pour order 15): 2025,2180 2025,2250 1025,2250 1025,2010 2640,2010 2640,2600 2460,2600 2460,2495 2165,2495 2165,2180
22 on Top Layer " " (solid, pour order 16): 2140,3244 2010,3244 2010,3170 2140,3170 2140,3080 2255,3080 2255,2820 2030,2820 2030,2845 1300,2845 1300,3400 2140,3400
1 on Top Layer " " (solid, pour order 17): 2160,3470 2005,3470 2005,3410 1025,3410 1025,4625 2640,4625 2640,3000 2460,3000 2460,3110 2160,3110
42 on Top Layer " " (solid, pour order 18): 2045,2495 2145,2495 2145,2440 2045,2440
42 on Top Layer " " (solid, pour order 19): 2145,2250 2145,2200 2035,2200 2035,2250
43 on Top Layer " " (solid, pour order 20): 2280,2865 2375,2865 2375,2820 2280,2820
43 on Top Layer " " (solid, pour order 21): 2280,3080 2280,3045 2390,3045 2390,3080
44 on Top Layer " " (solid, pour order 22): 2280,2560 2440,2560 2440,2515 2280,2515
44 on Top Layer " " (solid, pour order 23): 2370,2790 2370,2730 2280,2730 2280,2790
41 on Top Layer " " (solid, pour order 24): 2025,3450 2025,3410 2140,3410 2140,3450
21 on Top Layer " " (solid, pour order 25): 2640,2810 2517,2810 2517,2780 2640,2780 2640,2620 2439,2620 2439,2575 2280,2575 2280,2720 2390,2720 2390,2885 2280,2885 2280,3035 2400,3035 2440,3035 2440,2979 2640,2979
25 on Top Layer " " (solid, pour order 26): 2145,2260 1300,2260 1300,2765 2030,2765 2030,2790 2255,2790 2255,2515 2035,2515 2035,2430 2145,2430
0 on Top Layer " " (solid, pour order 42): 2650,2365 3100,2365 3100,2325 2950,2325 2950,2360 2650,2360 2650,1025 4825,1025 4825,4625 2650,4625 2650,2810 2785,2810 2784,2780 2650,2780
17 on MidLayer2 " " (solid, pour order 7): 1025,1025 2640,1025 2640,2000 1025,2000
1 on MidLayer2 " " (solid, pour order 8): 2065,3410 2065,3455 2115,3455 2115,3410 2160,3410 2160,3110 2460,3110 2460,3000 2640,3000 2640,4625 1025,4625 1025,3410
22 on MidLayer2 " " (solid, pour order 9): 2140,3245 2030,3245 2030,3190 2140,3190 2140,3080 2255,3080 2255,2820 2030,2820 2030,2845 1300,2845 1300,3400 2140,3400
21 on MidLayer2 " " (solid, pour order 10): 2280,2870 2345,2870 2345,2820 2280,2820 2280,2765 2380,2765 2380,2715 2280,2715 2280,2515 2300,2515 2300,2560 2345,2560 2345,2515 2439,2515 2439,2620 2640,2620 2640,2780 2595,2780 2595,2810 2640,2810 2640,2979 2499,2979 2440,2979 2440,3075 2390,3075 2390,3040 2340,3040 2340,3075 2280,3075
17 on MidLayer2 " " (solid, pour order 11): 2025,2250 2025,2215 2085,2215 2085,2250 2165,2250 2165,2495 2460,2495 2460,2600 2640,2600 2640,2010 1025,2010 1025,2250
25 on MidLayer2 " " (solid, pour order 12): 2035,2515 2035,2430 2145,2430 2145,2260 1300,2260 1300,2765 2030,2765 2030,2790 2255,2790 2255,2515
17 on Mid-Layer 4 " " (solid, pour order 33): 1025,2000 2640,2000 2640,1025 1025,1025
1 on Mid-Layer 4 " " (solid, pour order 34): 2065,3410 2065,3455 2115,3455 2115,3410 2160,3410 2160,3110 2460,3110 2460,3059 2460,3000 2640,3000 2640,4625 1025,4625 1025,3410
22 on Mid-Layer 4 " " (solid, pour order 35): 2140,3245 2030,3245 2030,3190 2140,3190 2140,3080 2255,3080 2255,2820 2030,2820 2030,2845 1300,2845 1300,3400 2140,3400
17 on Mid-Layer 4 " " (solid, pour order 36): 2025,2250 2025,2215 2085,2215 2085,2250 2165,2250 2165,2495 2460,2495 2460,2600 2640,2600 2640,2010 1025,2010 1025,2250
21 on Mid-Layer 4 " " (solid, pour order 37): 2280,2870 2345,2870 2345,2820 2280,2820 2280,2765 2380,2765 2380,2715 2280,2715 2280,2514 2300,2514 2300,2555 2345,2555 2345,2515 2439,2515 2439,2620 2640,2620 2640,2780 2595,2780 2595,2810 2640,2810 2640,2979 2440,2979 2440,3080 2390,3080 2390,3040 2335,3040 2335,3080 2280,3080
25 on Mid-Layer 4 " " (solid, pour order 38): 2035,2515 2035,2430 2145,2430 2145,2260 1300,2260 1300,2765 2030,2765 2030,2790 2255,2790 2255,2515
0 on Mid-Layer 3 " " (solid, pour order 39): 1025,2810 2595,2810 2595,2425 2960,2425 2960,2325 3100,2325 3100,2475 2700,2475 2700,2815 1025,2815 1025,4625 4825,4625 4825,1025 1025,1025
0 on MidLayer1 " " (solid, pour order 40): 1025,2815 2705,2815 2705,2775 2585,2775 2585,2810 1025,2810 1025,1025 4825,1025 4825,2360 3300,2360 3300,2325 2955,2325 2955,2365 4825,2365 4825,4625 1025,4625
0 on MidLayer2 " " (solid, pour order 41): 2650,2810 2700,2810 2700,2780 2650,2780 2650,2365 3100,2365 3100,2320 2955,2320 2955,2360 2650,2360 2650,1025 4825,1025 4825,4625 2650,4625
0 on Mid-Layer 4 " " (solid, pour order 46): 2650,2810 2700,2810 2700,2780 2650,2780 2650,2365 3100,2365 3100,2325 2925,2325 2925,2360 2650,2360 2650,1025 4825,1025 4825,4625 2650,4625
no net on Top Paste "Top Layer-No Net" (solid, remove dead copper): 2309.11,2572.32 2309.11,2599.87 2277.62,2599.87 2277.62,2572.32
no net on Top Paste "Top Layer-No Net" (solid, remove dead copper): 2309.11,2626.25 2309.11,2653.81 2277.62,2653.81 2277.62,2626.25
no net on Top Paste "Top Layer-No Net" (solid, remove dead copper): 2309.11,2680.19 2309.11,2707.75 2277.62,2707.75 2277.62,2680.19
no net on Top Paste "Top Layer-No Net" (solid, remove dead copper): 2309.11,2734.13 2309.11,2761.69 2277.62,2761.69 2277.62,2734.13
no net on Top Paste "Top Layer-No Net" (solid, remove dead copper): 2092.38,2734.13 2092.38,2761.68 2060.89,2761.68 2060.89,2734.13
no net on Top Paste "Top Layer-No Net" (solid, remove dead copper): 2092.38,2680.19 2092.38,2707.75 2060.89,2707.75 2060.89,2680.19
no net on Top Paste "Top Layer-No Net" (solid, remove dead copper): 2092.38,2626.25 2092.38,2653.81 2060.89,2653.81 2060.89,2626.25
no net on Top Paste "Top Layer-No Net" (solid, remove dead copper): 2092.38,2572.31 2092.38,2599.87 2060.89,2599.87 2060.89,2572.31
no net on Top Solder "Top Layer-No Net" (solid, remove dead copper): 2309.11,2572.32 2309.11,2599.87 2277.62,2599.87 2277.62,2572.32
no net on Top Solder "Top Layer-No Net" (solid, remove dead copper): 2309.11,2626.25 2309.11,2653.81 2277.62,2653.81 2277.62,2626.25
no net on Top Solder "Top Layer-No Net" (solid, remove dead copper): 2309.11,2680.19 2309.11,2707.75 2277.62,2707.75 2277.62,2680.19
no net on Top Solder "Top Layer-No Net" (solid, remove dead copper): 2309.11,2734.13 2309.11,2761.69 2277.62,2761.69 2277.62,2734.13
no net on Top Solder "Top Layer-No Net" (solid, remove dead copper): 2092.38,2734.13 2092.38,2761.68 2060.89,2761.68 2060.89,2734.13
no net on Top Solder "Top Layer-No Net" (solid, remove dead copper): 2092.38,2680.19 2092.38,2707.75 2060.89,2707.75 2060.89,2680.19
no net on Top Solder "Top Layer-No Net" (solid, remove dead copper): 2092.38,2626.25 2092.38,2653.81 2060.89,2653.81 2060.89,2626.25
no net on Top Solder "Top Layer-No Net" (solid, remove dead copper): 2092.38,2572.31 2092.38,2599.87 2060.89,2599.87 2060.89,2572.31
no net on Top Solder "Top Layer-No Net" (solid, remove dead copper): 2092.48,2577.24 2261.77,2577.24 2261.77,2756.76 2092.48,2756.76

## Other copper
Multi-Layer:
  the board outline again, w1

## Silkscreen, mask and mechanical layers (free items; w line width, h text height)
Top Overlay:
  text "Note :" at 1075,4365 h30
  text "For Dither off option, place zero Ohm Resistor for Cdith." at 1110,4290 h30
  text "For CCM and Hiccup off option," at 1110,4180 h30
  text "Place zero ohm resistor for Cisns and Risns." at 1225,4105 h30
  text "connect TP_SNS to GND." at 1225,4035 h30
  text "Cbulk" at 2465,3984 h30
  text "Cin" at 2795,3120 h30
  text "Coutx" at 2795,2415 h30
  text "Coutx2" at 2710,2070 h30
  text "Cout" at 2915,1635 h30
Bottom Overlay:
  text "Ccomp" at 3464,2878 h30 r180
  text "Coutx3" at 2470,2490 h30 r180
